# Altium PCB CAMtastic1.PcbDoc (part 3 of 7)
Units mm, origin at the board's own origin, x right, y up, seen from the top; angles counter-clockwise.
Board outline 150.22 x 135.24 mm, 5 copper layers (Top Layer, Layer 1, Mid-Layer 1, Layer 2, Bottom Layer), stack 0.461 mm thick; 0 components, 362 nets, 2885 pads, 0 vias.
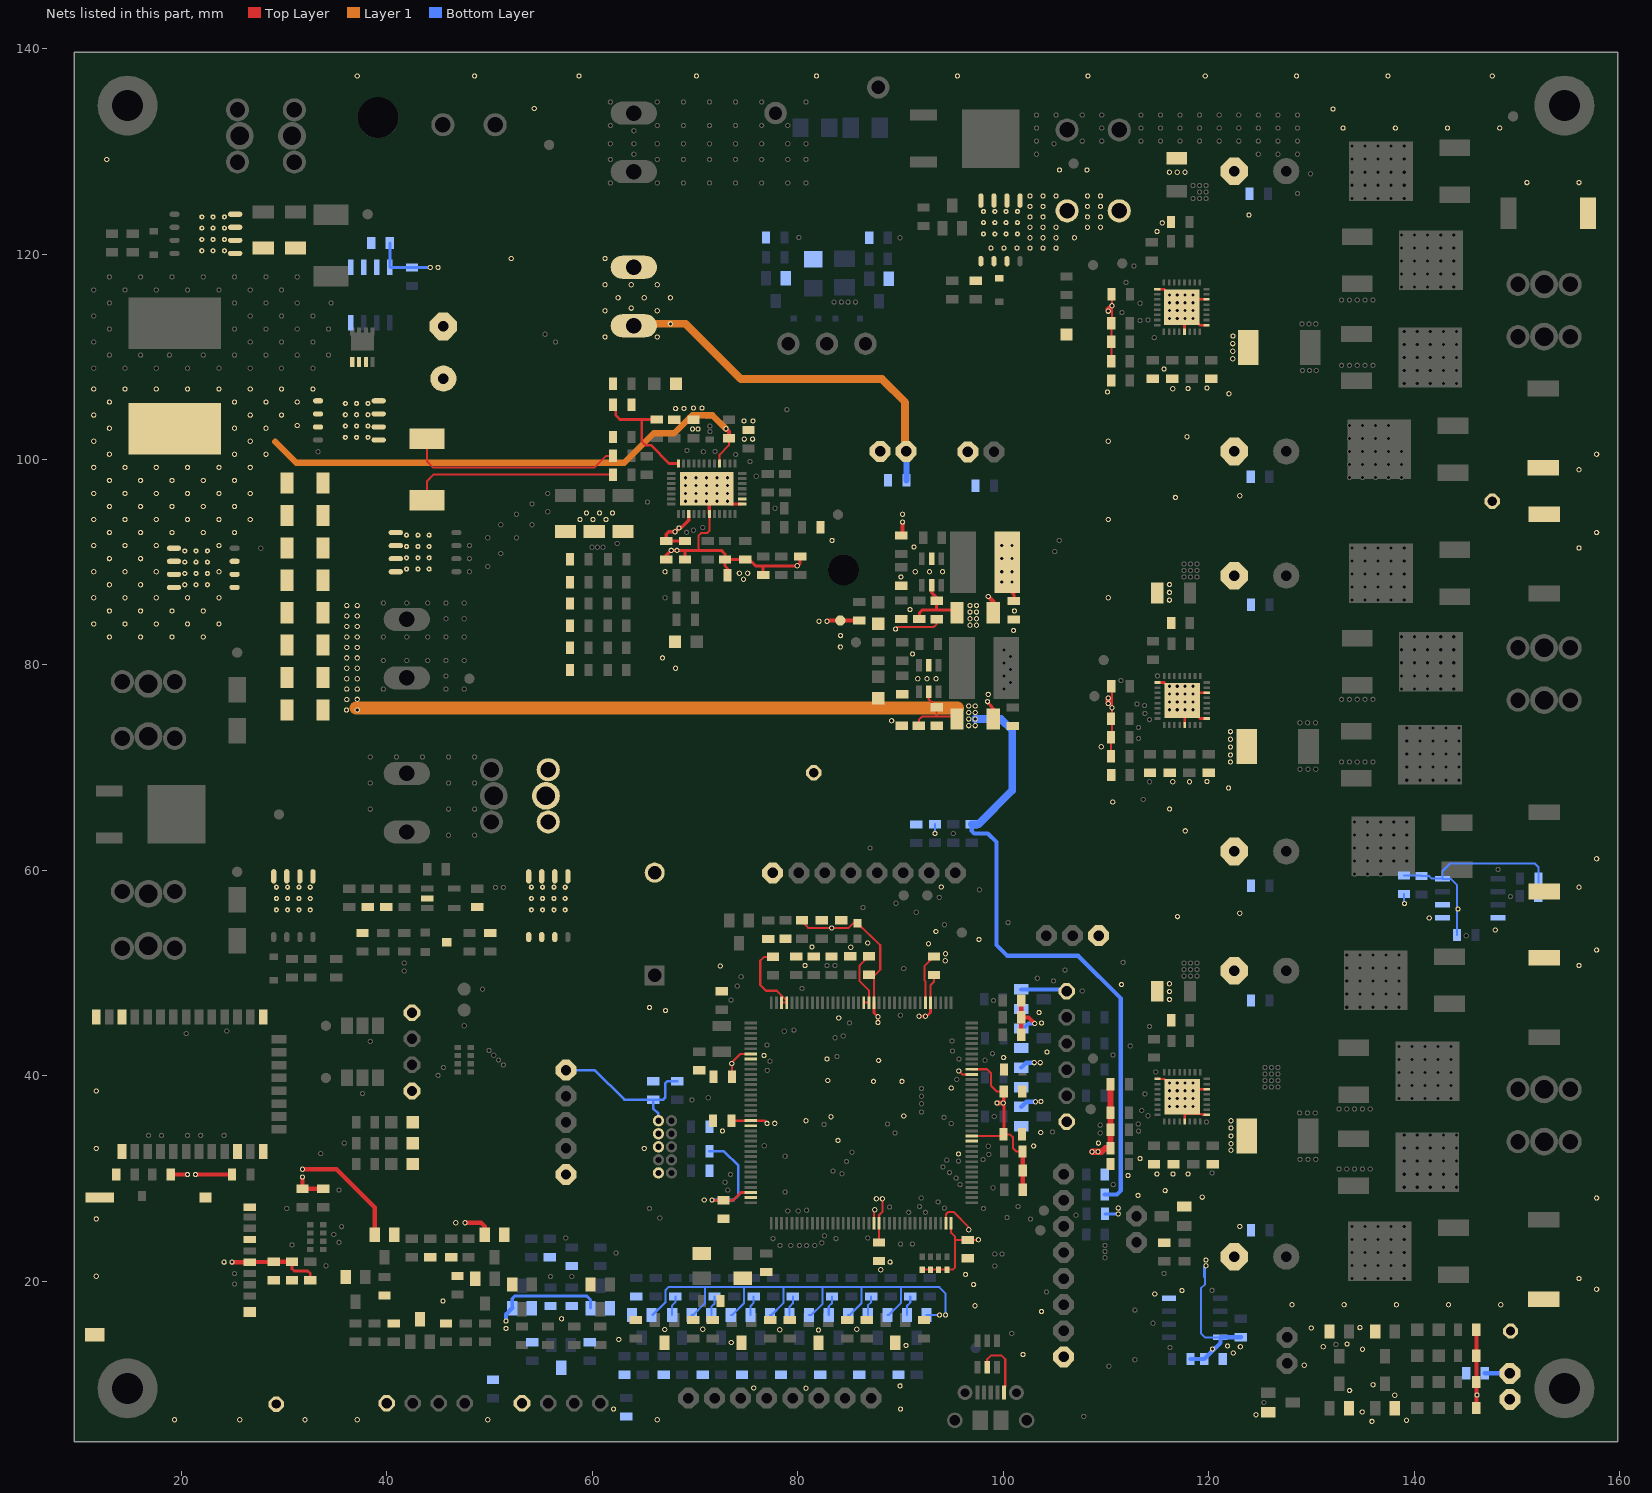
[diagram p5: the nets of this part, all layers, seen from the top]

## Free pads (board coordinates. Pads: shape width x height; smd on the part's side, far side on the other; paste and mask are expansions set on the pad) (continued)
  rect 0.279x1.219 smd paste+0 mask+0.102: 1(77.411,25.654) 1(77.411,47.142) 1(77.911,25.654) 1(77.911,47.142) 1(78.411,25.654) 1(78.411,47.142) 1(78.911,25.654) 1(78.911,47.142) 1(79.411,25.654) 1(79.411,47.142) 1(79.911,25.654) 1(79.911,47.142) 1(80.411,25.654) 1(80.411,47.142) 1(80.911,25.654) 1(80.911,47.142) 1(81.411,25.654) 1(81.411,47.142) 1(81.911,25.654) 1(81.911,47.142) 1(82.411,25.654) 1(82.411,47.142) 1(82.911,25.654) 1(82.911,47.142) 1(83.411,25.654) 1(83.411,47.142) 1(83.911,25.654) 1(83.911,47.142) 1(84.411,25.654) 1(84.411,47.142) 1(84.911,25.654) 1(84.911,47.142) 1(85.411,25.654) 1(85.411,47.142) 1(85.911,25.654) 1(85.911,47.142) 1(86.411,25.654) 1(86.411,47.142) 1(86.911,25.654) 1(86.911,47.142) 1(87.411,25.654) 1(87.411,47.142) 1(87.911,25.654) 1(87.911,47.142) 1(88.411,25.654) 1(88.411,47.142) 1(88.911,25.654) 1(88.911,47.142) 1(89.411,25.654) 1(89.411,47.142) 1(89.911,25.654) 1(89.911,47.142) 1(90.411,25.654) 1(90.411,47.142) 1(90.911,25.654) 1(90.911,47.142) 1(91.411,25.654) 1(91.411,47.142) 1(91.911,25.654) 1(91.911,47.142) 1(92.411,25.654) 1(92.411,47.142) 1(92.911,25.654) 1(92.911,47.142) 1(93.411,25.654) 1(93.411,47.142) 1(93.911,25.654) 1(93.911,47.142) 1(94.411,25.654) 1(94.411,47.142) 1(94.911,25.654) 1(94.911,47.142)
  oct 1.93x1.93 / inner round 1.784 / far side oct 1.93x1.93 hole 1.016 rot 135 mask+0.102: 1(77.545,59.758) 1(88.006,100.804) 1(90.546,100.804) 1(96.549,100.754) 1(99.088,100.754) 1(109.275,53.645)
  round 2.184 hole 1.3 mask+0.102: 1(77.825,133.722) 1(79.075,111.272) 1(82.825,111.272) 1(86.575,111.272) 1(87.825,136.222)
  rect 0.6x0.6 smd far side paste+0 mask+0.102: 1(79.593,113.716) 1(81.992,113.716) 1(83.657,113.716) 1(86.056,113.716)
  rect 1.6x1.8 smd far side paste+0 mask+0.102: 1(80.255,132.296) 1(83.055,132.296)
  rect 1.8x1.6 smd far side paste+0 mask+0.102: 1(81.487,116.685) 1(81.487,119.485)
  round 3 hole 3 mask+0.102: 1(84.435,89.258)
  rect 2x1.6 smd far side paste+0 mask+0.102: 1(84.535,116.761) 1(84.535,119.561)
  rect 1.6x2 smd far side paste+0 mask+0.102: 1(85.157,132.296) 1(87.957,132.296)
  rect 0.8x0.8 smd paste+0 mask+0.102: 1(85.805,53.352) 1(85.805,54.852)
  rect 0.55x1.2 smd paste+0 mask+0.102: 1(91.79,77.389) 1(91.79,79.989) 1(92.069,87.752) 1(92.069,90.352) 1(92.739,77.389) 1(92.739,79.989) 1(93.019,87.752) 1(93.019,90.352) 1(93.689,77.389) 1(93.689,79.989) 1(93.969,87.752) 1(93.969,90.352) 1(97.479,11.628) 1(97.479,14.229) 1(98.429,11.628) 1(98.429,14.229) 1(99.379,11.628) 1(99.379,14.229)
  rect 0.5x0.65 smd paste+0 mask+0.102: 1(92.098,21.143) 1(92.098,22.393) 1(92.898,21.143) 1(92.898,22.393) 1(93.698,21.143) 1(93.698,22.393) 1(94.498,21.143) 1(94.498,22.393)
  round 1.508 hole 1 mask+0.102: 1(95.27,6.469) 1(102.27,6.469)
  rect 2.5x6 smd paste+0 mask+0.102: 1(95.974,79.705) 1(96.075,89.992) 1(100.274,79.705) 1(100.375,89.992)
  round 1.45 hole 0.85 mask+0.102: 1(96.27,9.169) 1(101.27,9.169)
  rect 0.4x1.35 smd paste+0 mask+0.102: 1(97.47,9.169) 1(98.12,9.169) 1(98.77,9.169) 1(99.42,9.169) 1(100.07,9.169)
  rect 1.5x1.9 smd paste+0 mask+0.102: 1(97.77,6.469) 1(99.77,6.469)
  rect 1.4x1 smd far side paste+0 mask+0.102: 1(101.749,35.093) 1(101.749,36.993) 1(101.749,38.903) 1(101.749,40.803) 1(101.749,42.713) 1(101.749,44.613) 1(101.749,46.523) 1(101.749,48.423) 1(103.949,36.043) 1(103.949,39.853) 1(103.949,43.663) 1(103.949,47.473)
  rect 1.2x2 smd paste+0 mask+0.102: 1(114.967,48.24) 1(114.967,87.007) 1(118.167,48.24) 1(118.167,87.007)
  rect 0.6x0.25 smd paste+0 mask+0.102: 1(114.98,113.083) 1(114.98,113.583) 1(114.98,114.083) 1(114.98,114.583) 1(114.98,115.083) 1(114.98,115.583) 1(114.98,116.083) 1(114.98,116.583) 1(115.005,36.203) 1(115.005,36.703) 1(115.005,37.203) 1(115.005,37.703) 1(115.005,38.203) 1(115.005,38.703) 1(115.005,39.203) 1(115.005,39.703) 1(115.005,74.792) 1(115.005,75.292) 1(115.005,75.792) 1(115.005,76.292) 1(115.005,76.792) 1(115.005,77.292) 1(115.005,77.792) 1(115.005,78.292) 1(119.78,113.083) 1(119.78,113.583) 1(119.78,114.083) 1(119.78,114.583) 1(119.78,115.083) 1(119.78,115.583) 1(119.78,116.083) 1(119.78,116.583) 1(119.805,36.203) 1(119.805,36.703) 1(119.805,37.203) 1(119.805,37.703) 1(119.805,38.203) 1(119.805,38.703) 1(119.805,39.203) 1(119.805,39.703) 1(119.805,74.792) 1(119.805,75.292) 1(119.805,75.792) 1(119.805,76.292) 1(119.805,76.792) 1(119.805,77.292) 1(119.805,77.792) 1(119.805,78.292)
  rect 1.4x1 smd paste+0 mask+0.102: 1(115.414,26.34) 1(117.614,25.39) 1(117.614,27.29) 1(125.781,7.254) 1(125.781,9.154) 1(128.181,8.204)
  rect 0.25x0.6 smd paste+0 mask+0.102: 1(115.63,112.433) 1(115.63,117.233) 1(115.655,35.553) 1(115.655,40.353) 1(115.655,74.142) 1(115.655,78.942) 1(116.13,112.433) 1(116.13,117.233) 1(116.155,35.553) 1(116.155,40.353) 1(116.155,74.142) 1(116.155,78.942) 1(116.63,112.433) 1(116.63,117.233) 1(116.655,35.553) 1(116.655,40.353) 1(116.655,74.142) 1(116.655,78.942) 1(117.13,112.433) 1(117.13,117.233) 1(117.155,35.553) 1(117.155,40.353) 1(117.155,74.142) 1(117.155,78.942) 1(117.63,112.433) 1(117.63,117.233) 1(117.655,35.553) 1(117.655,40.353) 1(117.655,74.142) 1(117.655,78.942) 1(118.13,112.433) 1(118.13,117.233) 1(118.155,35.553) 1(118.155,40.353) 1(118.155,74.142) 1(118.155,78.942) 1(118.63,112.433) 1(118.63,117.233) 1(118.655,35.553) 1(118.655,40.353) 1(118.655,74.142) 1(118.655,78.942) 1(119.13,112.433) 1(119.13,117.233) 1(119.155,35.553) 1(119.155,40.353) 1(119.155,74.142) 1(119.155,78.942)
  rect 1.4x0.52 smd far side paste+0 mask+0.102: 1(116.124,14.554) 1(116.124,15.824) 1(116.124,17.094) 1(116.124,18.364) 1(121.125,14.554) 1(121.125,15.824) 1(121.125,17.094) 1(121.125,18.364)
  rect 2x1.2 smd paste+0 mask+0.102: 1(116.872,126.111) 1(116.872,129.311)
  rect 3.45x3.45 smd paste+0 mask+0.102: 1(117.38,114.833) 1(117.405,37.953) 1(117.405,76.542)
  oct 2.54x2.54 / inner round 2.347 / far side oct 2.54x2.54 hole 1.016 rot 45 mask+0.102: 1(122.46,22.403) 1(122.46,50.241) 1(122.46,61.849) 1(122.46,88.697) 1(122.46,100.787) 1(122.46,128.067)
  rect 2x3.4 smd paste+0 mask+0.102: 1(123.676,34.169) 1(123.702,72.072) 1(123.854,110.896) 1(129.676,34.169) 1(129.702,72.072) 1(129.854,110.896)
  rect 3x1.6 smd paste+0 mask+0.102: 1(134.093,29.318) 1(134.093,33.888) 1(134.114,38.183) 1(134.114,42.753) 1(134.347,68.974) 1(134.347,73.544) 1(134.373,107.646) 1(134.373,112.216) 1(134.444,78.017) 1(134.444,82.587) 1(134.444,117.12) 1(134.444,121.69) 1(143.435,47.036) 1(143.435,51.606) 1(143.771,98.705) 1(143.771,103.275) 1(143.821,20.646) 1(143.821,25.216) 1(143.943,86.628) 1(143.943,91.198) 1(143.943,125.782) 1(143.943,130.352) 1(144.152,60.06) 1(144.152,64.63)
  rect 6.2x5.8 smd paste+0 mask+0.102: 1(136.255,49.321) 1(136.591,100.99) 1(136.641,22.931) 1(136.763,88.913) 1(136.763,128.067) 1(136.972,62.345) 1(141.273,31.603) 1(141.294,40.468) 1(141.527,71.259) 1(141.624,80.302) 1(141.624,119.405)
  rect 6.2x5.8 / inner round 0.508 / far side round 0.508 hole 0.305 mask+0.102: 1(141.553,109.931)
  round 0.508 smd paste-0.254 mask+0.61: 1(141.558,109.931)
  rect 1.5x0.55 smd far side paste+0 mask+0.102: 1(142.747,55.397) 1(142.747,56.667) 1(142.747,57.937) 1(142.747,59.207) 1(148.147,55.397) 1(148.147,56.667) 1(148.147,57.937) 1(148.147,59.207)
  rect 1.52x3.07 smd paste+0 mask+0.102: 1(149.176,123.977) 1(156.907,123.977)
  rect 3.07x1.52 smd paste+0 mask+0.102: 1(152.559,99.183) 1(152.559,106.913) 1(152.584,18.264) 1(152.584,25.994) 1(152.635,43.765) 1(152.635,51.496) 1(152.635,86.952) 1(152.635,94.682) 1(152.661,57.945) 1(152.661,65.676)

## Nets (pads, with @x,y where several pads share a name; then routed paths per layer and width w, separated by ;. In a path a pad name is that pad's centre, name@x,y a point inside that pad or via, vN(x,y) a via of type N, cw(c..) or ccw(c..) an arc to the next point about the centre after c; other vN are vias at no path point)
$Net0: pad.1@11.542,14.818 pad.1@11.692,45.738 pad.1@11.705,20.498 pad.1@11.705,26.086 pad.1@11.705,32.944 pad.1@11.705,38.532 pad.1@12.042,28.168 pad.1@12.721,129.21 pad.1@13.637,30.404 pad.1@14.206,32.631 pad.1@14.206,45.738 pad.1@19.325,6.528 pad.1@21.973,120.321 pad.1@21.973,121.421 pad.1@21.973,122.521 pad.1@21.973,123.621 pad.1@22.342,28.168 pad.1@23.073,120.321 pad.1@23.073,121.421 pad.1@23.073,122.521 pad.1@23.073,123.621 pad.1@24.173,120.321 pad.1@24.173,121.421 pad.1@24.173,122.521 pad.1@24.173,123.621 pad.1@25.167,87.554 pad.1@25.167,88.824 pad.1@25.167,90.094 pad.1@25.222,120.066 pad.1@25.222,121.336 pad.1@25.222,122.606 pad.1@25.222,123.876 pad.1@25.454,32.631 pad.1@25.675,6.528 pad.1@26.642,17.018 pad.1@26.642,24.068 pad.1@26.642,27.218 pad.1@27.953,32.631 pad.1@27.953,45.738 pad.1@27.961,120.597 pad.1@28.977,20.106 pad.1@28.977,59.418 pad.1@29.231,8.052 pad.1@29.232,56.168 pad.1@29.232,57.268 pad.1@29.232,58.368 pad.1@30.27,75.616 pad.1@30.27,78.773 pad.1@30.27,81.929 pad.1@30.27,85.086 pad.1@30.27,88.243 pad.1@30.27,91.4 pad.1@30.27,94.557 pad.1@30.27,97.714 pad.1@30.247,59.418 pad.1@30.332,56.168 pad.1@30.332,57.268 pad.1@30.332,58.368 pad.1@30.755,20.106 pad.1@31.101,120.597 pad.1@31.431,56.168 pad.1@31.431,57.268 pad.1@31.431,58.368 pad.1@31.517,59.418 pad.1@32.025,6.528 pad.1@32.532,56.168 pad.1@32.532,57.268 pad.1@32.532,58.368 pad.1@32.787,59.418 pad.1@35.986,20.428 pad.1@36.47,113.302 pad.1@36.47,118.702 pad.1@37.74,118.702 pad.1@37.105,6.528 pad.1@37.105,137.338 pad.1@37.613,53.91 pad.1@38.48,121.082 pad.1@38.128,56.428 pad.1@39.01,118.702 pad.1@39.755,18.633 pad.1@39.915,56.428 pad.1@39.958,8.136 pad.1@40.669,15.911 pad.1@40.705,24.544 pad.1@42.439,38.532 pad.1@42.507,31.42 pad.1@42.507,33.452 pad.1@42.507,35.484 pad.1@43.209,16.315 pad.1@43.927,57.278 pad.1@44.2,22.341 pad.1@45.445,18.085 pad.1@45.487,112.954 pad.1@45.749,15.911 pad.1@45.825,53.01 pad.1@46.257,22.341 pad.1@46.867,20.534 pad.1@48.535,137.338 pad.1@48.584,20.25 pad.1@48.789,56.428 pad.1@49.805,6.528 pad.1@50.059,53.91 pad.1@50.321,10.425 pad.1@51.424,24.544 pad.1@52.091,119.558 pad.1@52.191,19.691 pad.1@53.141,8.136 pad.1@53.795,53.518 pad.1@54.091,17.391 pad.1@54.157,14.083 pad.1@54.335,134.163 pad.1@55.065,53.518 pad.1@55.859,22.341 pad.1@55.909,17.591 pad.1@56.335,53.518 pad.1@56.951,11.6 pad.1@57.002,16.358 pad.1@57.81,79.509 pad.1@57.81,81.668 pad.1@57.81,83.827 pad.1@57.81,85.986 pad.1@57.81,88.044 pad.1@57.81,90.304 pad.1@57.383,92.987 pad.1@57.425,30.404 pad.1@57.992,17.591 pad.1@57.992,21.503 pad.1@58.78,94.158 pad.1@58.695,137.338 pad.1@59.415,94.793 pad.1@59.745,14.083 pad.1@59.811,19.691 pad.1@60.05,94.158 pad.1@60.177,92.987 pad.1@60.685,94.793 pad.1@61.32,94.158 pad.1@61.711,17.391 pad.1@61.955,94.793 pad.1@62.056,7.569 pad.1@62.564,14.351 pad.1@62.971,92.987 pad.1@63.123,10.911 pad.1@63.301,6.847 pad.1@63.797,105.334 pad.1@63.841,16.729 pad.1@64.215,16.242 pad.1@64.266,18.531 pad.1@65.045,32.944 pad.1@65.553,46.66 pad.1@65.917,39.483 pad.1@66.061,59.788 pad.1@66.315,6.528 pad.1@66.425,30.556 pad.1@66.425,33.096 pad.1@66.425,34.366 pad.1@66.823,80.696 pad.1@66.933,10.911 pad.1@67.009,14.038 pad.1@67.19,90.261 pad.1@67.035,15.316 pad.1@67.67,91.161 pad.1@67.077,89.078 pad.1@67.111,46.355 pad.1@67.761,16.721 pad.1@67.977,103.872 pad.1@68.042,82.263 pad.1@68.076,18.531 pad.1@68.093,79.68 pad.1@68.101,104.953 pad.1@68.127,107.366 pad.1@68.228,91.161 pad.1@68.914,104.978 pad.1@69.006,90.273 pad.1@69.067,95.936 pad.1@69.067,96.698 pad.1@69.067,97.46 pad.1@69.067,98.222 pad.1@69.752,102.972 pad.1@69.803,16.242 pad.1@69.829,105.004 pad.1@69.831,103.872 pad.1@70.083,95.936 pad.1@70.083,96.698 pad.1@70.083,97.46 pad.1@70.083,98.222 pad.1@70.125,137.338 pad.1@70.286,102.972 pad.1@70.413,40.553 pad.1@70.648,22.714 pad.1@70.667,105.004 pad.1@70.743,10.911 pad.1@70.743,15.342 pad.1@71.099,95.936 pad.1@71.099,96.698 pad.1@71.099,97.46 pad.1@71.099,98.222 pad.1@71.127,97.155 pad.1@71.377,94.703 pad.1@71.389,30.759 pad.1@71.389,35.052 pad.1@71.571,16.721 pad.1@71.708,16.242 pad.1@71.748,35.636 pad.1@71.774,39.929 pad.1@71.886,18.531 pad.1@72.75,26.1 pad.1@72.115,95.936 pad.1@72.115,96.698 pad.1@72.115,97.46 pad.1@72.115,98.222 pad.1@72.445,50.698 pad.1@72.456,18.085 pad.1@72.597,48.246 pad.1@72.648,34.646 pad.1@72.905,90.261 pad.1@73.131,95.936 pad.1@73.131,96.698 pad.1@73.131,97.46 pad.1@73.131,98.222 pad.1@73.144,88.748 pad.1@73.512,14.046 pad.1@74.299,88.925 pad.1@74.502,14.038 pad.1@74.553,10.911 pad.1@74.579,95.655 pad.1@74.579,96.155 pad.1@74.648,20.314 pad.1@74.705,88.341 pad.1@74.756,103.759 pad.1@74.782,101.981 pad.1@74.861,90.261 pad.1@75.62,103.759 pad.1@75.112,88.925 pad.1@75.191,102.881 pad.1@75.381,16.721 pad.1@75.417,28.148 pad.1@75.417,35.148 pad.1@75.417,41.648 pad.1@75.594,101.981 pad.1@75.696,9.627 pad.1@75.696,18.531 pad.1@76.613,88.762 pad.1@76.712,41.986 pad.1@76.905,121.61 pad.1@76.915,20.919 pad.1@77.118,53.329 pad.1@77.296,16.242 pad.1@77.545,59.758 pad.1@77.576,51.598 pad.1@78.236,15.291 pad.1@78.363,10.911 pad.1@78.411,47.142 pad.1@78.795,53.354 pad.1@78.805,117.63 pad.1@78.911,47.142 pad.1@79.191,16.721 pad.1@79.201,16.242 pad.1@79.506,18.531 pad.1@79.836,51.624 pad.1@79.938,89.662 pad.1@80.7,50.749 pad.1@80.217,90.559 pad.1@80.776,9.601 pad.1@80.776,35.636 pad.1@81.36,52.553 pad.1@81.487,119.485 pad.1@81.538,51.624 pad.1@81.555,69.52 pad.1@81.809,137.338 pad.1@81.995,14.038 pad.1@81.995,15.265 pad.1@82.2,93.396 pad.1@82.91,39.548 pad.1@82.173,10.911 pad.1@82.325,55.154 pad.1@82.833,41.656 pad.1@83.001,16.721 pad.1@83.214,36.017 pad.1@83.265,51.624 pad.1@83.316,18.531 pad.1@83.333,92.126 pad.1@83.905,33.727 pad.1@83.976,45.644 pad.1@84.23,55.154 pad.1@84.129,81.763 pad.1@84.154,82.855 pad.1@84.789,16.242 pad.1@85.094,51.649 pad.1@85.145,52.527 pad.1@85.729,15.342 pad.1@85.983,10.911 pad.1@86.411,47.142 pad.1@86.694,16.242 pad.1@86.796,52.934 pad.1@86.811,16.721 pad.1@86.911,47.142 pad.1@86.923,51.649 pad.1@86.955,121.59 pad.1@87.126,18.531 pad.1@87.355,39.472 pad.1@87.411,25.654 pad.1@87.482,26.975 pad.1@87.837,76.75 pad.1@87.837,84.015 pad.1@87.863,41.504 pad.1@87.888,21.985 pad.1@88.006,100.804 pad.1@88.066,21.133 pad.1@88.98,21.869 pad.1@88.783,97.968 pad.1@88.855,117.61 pad.1@89.128,74.574 pad.1@89.488,14.038 pad.1@89.514,83.49 pad.1@89.793,10.911 pad.1@89.945,9.83 pad.1@89.996,7.569 pad.1@90.022,88.57 pad.1@90.53,13.767 pad.1@90.072,84.469 pad.1@90.072,87.721 pad.1@90.123,39.472 pad.1@90.123,74.081 pad.1@90.149,77.154 pad.1@90.301,36.093 pad.1@90.621,16.721 pad.1@90.911,85.395 pad.1@90.936,18.531 pad.1@91.52,64.476 pad.1@91.165,81.077 pad.1@91.292,91.491 pad.1@91.419,89.078 pad.1@91.673,78.664 pad.1@92.282,16.242 pad.1@92.411,47.142 pad.1@92.562,78.664 pad.1@92.714,52.857 pad.1@92.739,79.989 pad.1@92.816,89.078 pad.1@93.019,90.352 pad.1@93.247,51.624 pad.1@93.425,54.051 pad.1@93.451,78.664 pad.1@93.501,74.081 pad.1@93.501,84.444 pad.1@93.959,58.395 pad.1@94.34,51.206 pad.1@94.086,89.078 pad.1@94.365,51.892 pad.1@94.411,25.654 pad.1@94.924,38.811 pad.1@95.66,40.488 pad.1@95.525,137.338 pad.1@95.635,32.41 pad.1@96.321,20.676 pad.1@96.524,22.239 pad.1@96.549,100.754 pad.1@96.626,25.019 pad.1@96.905,33.648 pad.1@96.905,40.148 pad.1@97.108,19.685 pad.1@97.235,17.628 pad.1@97.289,97.46 pad.1@97.303,117.41 pad.1@97.616,53.289 pad.1@97.811,119.304 pad.1@98.429,11.628 pad.1@98.454,76.429 pad.1@98.531,77.14 pad.1@98.531,86.665 pad.1@99.016,74.727 pad.1@99.016,85.09 pad.1@99.081,119.304 pad.1@99.589,117.66 pad.1@100.07,9.169 pad.1@100.029,41.783 pad.1@100.069,40.615 pad.1@100.351,119.304 pad.1@100.918,74.055 pad.1@100.994,83.363 pad.1@101.02,84.419 pad.1@101.071,85.268 pad.1@101.749,35.093 pad.1@101.749,38.903 pad.1@101.749,42.713 pad.1@101.749,46.523 pad.1@101.818,34.315 pad.1@101.844,38.481 pad.1@101.909,12.878 pad.1@102.95,33.172 pad.1@103.484,46.177 pad.1@103.636,34.493 pad.1@103.712,17.069 pad.1@104.246,42.316 pad.1@105.465,128.194 pad.1@105.871,12.649 pad.1@106.151,35.535 pad.1@106.151,112.171 pad.1@108.132,128.194 pad.1@108.225,137.338 pad.1@109.249,33.452 pad.1@109.275,53.645 pad.1@109.529,72.034 pad.1@109.873,30.404 pad.1@110.43,31.42 pad.1@110.138,106.578 pad.1@110.215,86.538 pad.1@110.215,94.158 pad.1@110.215,101.778 pad.1@110.506,69.291 pad.1@110.511,107.696 pad.1@110.646,66.65 pad.1@111.485,48.895 pad.1@112.145,30.302 pad.1@113.11,28.372 pad.1@113.313,31.953 pad.1@114.66,31.409 pad.1@114.98,116.583 pad.1@114.279,69.509 pad.1@114.533,107.863 pad.1@114.736,18.771 pad.1@114.939,30.455 pad.1@114.964,122.199 pad.1@114.967,48.24 pad.1@114.967,87.007 pad.1@115.005,39.703 pad.1@115.005,78.292 pad.1@115.65,23.76 pad.1@115.65,108.814 pad.1@115.472,123.038 pad.1@115.752,28.829 pad.1@116.92,37.033 pad.1@116.92,37.795 pad.1@116.92,38.557 pad.1@116.92,39.319 pad.1@116.92,75.641 pad.1@116.92,76.403 pad.1@116.92,77.165 pad.1@116.92,77.927 pad.1@116.92,113.741 pad.1@116.92,114.503 pad.1@116.92,115.265 pad.1@116.92,116.027 pad.1@116.92,127.965 pad.1@116.124,18.364 pad.1@116.158,37.033 pad.1@116.158,37.795 pad.1@116.158,38.557 pad.1@116.158,39.319 pad.1@116.158,47.447 pad.1@116.158,48.209 pad.1@116.158,48.971 pad.1@116.158,75.641 pad.1@116.158,76.403 pad.1@116.158,77.165 pad.1@116.158,77.927 pad.1@116.158,86.309 pad.1@116.158,87.071 pad.1@116.158,87.833 pad.1@116.158,113.741 pad.1@116.158,114.503 pad.1@116.158,115.265 pad.1@116.158,116.027 pad.1@116.158,127.965 pad.1@116.184,65.989 pad.1@116.184,69.509 pad.1@116.328,123.114 pad.1@116.353,45.421 pad.1@116.353,84.086 pad.1@116.438,107.863 pad.1@116.488,68.631 pad.1@116.488,106.883 pad.1@116.514,30.455 pad.1@116.565,31.409 pad.1@116.742,96.317 pad.1@116.872,129.311 pad.1@116.946,55.499 pad.1@117.38,114.833 pad.1@117.63,112.433 pad.1@117.377,19.101 pad.1@117.405,37.953 pad.1@117.405,76.542 pad.1@117.614,27.29 pad.1@117.655,35.553 pad.1@117.655,74.142 pad.1@117.682,37.033 pad.1@117.682,37.795 pad.1@117.682,38.557 pad.1@117.682,39.319 pad.1@117.682,75.641 pad.1@117.682,76.403 pad.1@117.682,77.165 pad.1@117.682,77.927 pad.1@117.682,113.741 pad.1@117.682,114.503 pad.1@117.682,115.265 pad.1@117.682,116.027 pad.1@117.682,127.965 pad.1@117.708,63.856 pad.1@117.885,102.21 pad.1@117.987,30.455 pad.1@117.987,106.909 pad.1@118.114,68.631 pad.1@118.444,37.033 pad.1@118.444,37.795 pad.1@118.444,38.557 pad.1@118.444,39.319 pad.1@118.444,75.641 pad.1@118.444,76.403 pad.1@118.444,77.165 pad.1@118.444,77.927 pad.1@118.444,113.741 pad.1@118.444,114.503 pad.1@118.444,115.265 pad.1@118.444,116.027 pad.1@119.78,113.083 pad.1@119.78,115.583 pad.1@119.359,28.194 pad.1@119.655,137.338 pad.1@119.805,36.203 pad.1@119.805,38.703 pad.1@119.805,74.792 pad.1@119.805,77.292 pad.1@119.816,68.656 pad.1@119.816,106.959 pad.1@119.994,69.509 pad.1@120.248,107.863 pad.1@120.375,31.409 pad.1@121.353,12.446 pad.1@121.822,13.716 pad.1@121.924,68.021 pad.1@121.949,106.401 pad.1@122.46,22.403 pad.1@122.46,50.241 pad.1@122.46,61.849 pad.1@122.46,88.697 pad.1@122.46,100.787 pad.1@122.46,128.067 pad.1@122.102,70.561 pad.1@122.102,71.247 pad.1@122.102,72.009 pad.1@122.102,72.771 pad.1@122.102,73.508 pad.1@122.153,32.766 pad.1@122.153,33.401 pad.1@122.153,34.163 pad.1@122.153,34.925 pad.1@122.153,35.636 pad.1@122.328,109.804 pad.1@122.328,110.541 pad.1@122.328,111.277 pad.1@122.353,112.014 pad.1@122.381,13.03 pad.1@123.016,25.349 pad.1@123.016,55.829 pad.1@123.016,96.469 pad.1@123.067,13.64 pad.1@123.676,34.169 pad.1@123.702,72.072 pad.1@123.854,110.896 pad.1@123.905,123.8 pad.1@123.971,125.882 pad.1@124.072,98.323 pad.1@124.098,24.968 pad.1@124.098,47.346 pad.1@124.098,58.496 pad.1@124.098,85.877 pad.1@124.591,7.01 pad.1@125.781,7.254 pad.1@128.096,17.729 pad.1@128.545,137.338 pad.1@129.29,11.836 pad.1@129.976,15.469 pad.1@131.144,13.64 pad.1@131.746,15.119 pad.1@132.084,134.112 pad.1@133.71,9.373 pad.1@133.075,132.258 pad.1@133.176,17.729 pad.1@133.456,13.894 pad.1@133.646,7.639 pad.1@134.7,15.494 pad.1@134.929,7.29 pad.1@134.954,13.386 pad.1@135.869,6.375 pad.1@135.996,9.931 pad.1@136.191,15.119 pad.1@137.435,137.338 pad.1@138.091,7.639 pad.1@138.104,8.915 pad.1@138.155,132.258 pad.1@138.256,17.729 pad.1@138.995,57.698 pad.1@139.046,56.769 pad.1@139.247,6.477 pad.1@141.459,55.372 pad.1@142.747,55.397 pad.1@142.747,56.667 pad.1@143.235,132.258 pad.1@143.336,17.729 pad.1@145.053,11.049 pad.1@147.595,95.936 pad.1@147.595,137.338 pad.1@147.885,54.204 pad.1@148.147,55.397 pad.1@148.315,132.258 pad.1@148.416,17.729 pad.1@149.305,8.509 pad.1@149.373,15.164 pad.1@150.956,126.949 pad.1@152.559,99.183 pad.1@152.584,18.264 pad.1@152.635,51.496 pad.1@152.635,94.682 pad.1@152.661,57.945 pad.1@156.036,20.269 pad.1@156.036,50.749 pad.1@156.036,58.369 pad.1@156.036,91.389 pad.1@156.036,99.009 pad.1@156.036,126.949 pad.1@156.907,123.977 pad.1@157.755,19.228 pad.1@157.755,28.118 pad.1@157.755,52.248 pad.1@157.755,61.138 pad.1@157.755,92.888 pad.1@157.755,100.508 | length 118.5
  Top Layer w0.203: 70.311,91.161 70.311,92.583 70.565,92.837 71.149,92.837 71.377,93.064 pad.1@71.377,94.703 ; pad.1@77.576,51.598 77.565,51.587 76.712,51.587 76.331,51.206 76.331,48.844 76.89,48.285 77.957,48.285 78.922,47.32 78.922,47.168 78.911,47.157 pad.1@78.911,47.142 pad.1@78.411,47.142 ; pad.1@86.411,47.142 pad.1@86.911,47.142 86.911,48.323 86.008,49.225 86.008,50.724 86.034,50.749 86.034,50.76 pad.1@86.923,51.649 ; pad.1@87.411,25.654 87.411,26.904 pad.1@87.482,26.975 ; pad.1@89.514,83.49 89.717,83.693 93.222,83.693 93.501,83.972 pad.1@93.501,84.444 ; pad.1@92.411,47.142 92.411,47.141 92.435,47.117 92.435,49.174 92.333,49.276 92.333,50.709 pad.1@93.247,51.624 pad.1@92.892,51.511 ; pad.1@94.416,25.756 94.416,25.654 pad.1@94.411,25.654 94.416,25.659 94.416,26.518 94.644,26.746 95.152,26.746 96.626,25.273 pad.1@96.626,25.019 ; pad.1@95.66,40.488 96,40.148 pad.1@96.905,40.148 ; pad.1@98.429,11.628 98.429,12.421 98.81,12.802 99.801,12.802 100.182,12.421 100.182,9.703 100.08,9.601 100.08,8.748 pad.1@100.07,9.169 pad.1@100.055,8.839 ; pad.1@114.837,116.586 pad.1@114.98,116.583 ; pad.1@115.005,39.703 115.015,39.7 115.65,39.7 117.301,38.049 pad.1@117.405,37.953 ; pad.1@116.793,38.684 pad.1@117.405,37.953 ; pad.1@117.655,35.553 117.657,35.636 pad.1@117.657,36.271 ; pad.1@119.714,38.71 pad.1@119.805,38.703 ; pad.1@119.805,36.203 119.663,36.22 119.409,36.22 119.333,36.271 pad.1@117.657,36.271 ; pad.1@117.405,37.953 pad.1@117.657,36.271 ; pad.1@117.405,37.953 117.428,37.922 117.682,37.668 pad.1@117.657,36.271
  Top Layer w0.254: pad.1@114.98,116.583 115.63,116.583 pad.1@117.38,114.833 ; pad.1@115.005,78.292 115.655,78.292 pad.1@117.405,76.542 119.155,74.792 pad.1@119.805,74.792 ; pad.1@116.793,38.684 pad.1@119.714,38.71 ; pad.1@117.63,112.433 117.63,114.583 pad.1@117.38,114.833 ; pad.1@117.655,74.142 pad.1@117.655,76.292 ; pad.1@118.155,77.292 pad.1@119.805,77.292 ; pad.1@119.78,113.083 119.13,113.083 pad.1@117.38,114.833 ; pad.1@119.78,115.583 118.13,115.583 pad.1@117.38,114.833
  Top Layer w0.305: pad.1@67.19,90.261 67.19,90.681 pad.1@67.67,91.161 69.168,91.161 ; pad.1@69.006,90.273 69.006,91.145 69.168,91.161 ; pad.1@71.099,95.936 71.377,95.658 pad.1@71.377,94.703 ; pad.1@73.131,95.936 73.412,95.655 pad.1@74.579,95.655 ; pad.1@73.144,88.748 73.144,89.394 72.902,89.637 72.902,90.258 pad.1@72.905,90.261 ; pad.1@76.613,88.762 76.613,89.589 76.661,89.637 ; pad.1@80.217,90.559 80.217,89.916 79.938,89.637 76.661,89.637 ; pad.1@98.454,76.429 99.016,75.766 pad.1@99.016,74.727 ; pad.1@117.655,76.292 pad.1@117.405,76.542 pad.1@118.155,77.292 ; 69.168,91.161 70.311,91.161 72.546,91.161 72.902,90.805 72.902,90.263 pad.1@72.905,90.261 ; pad.1@72.905,90.261 pad.1@74.861,90.261 75.275,90.261 75.899,89.637 76.661,89.637
  Top Layer w0.406: pad.1@98.531,86.665 99.016,86.18 pad.1@99.016,85.09
  Bottom Layer w0.203: pad.1@67.761,16.721 67.761,17.668 68.076,17.983 pad.1@68.076,18.531 ; pad.1@71.571,16.721 71.571,17.516 71.886,17.831 pad.1@71.886,18.531 ; pad.1@75.381,16.721 75.381,17.592 75.696,17.907 pad.1@75.696,18.531 ; pad.1@79.191,16.721 79.191,17.541 79.506,17.856 pad.1@79.506,18.531 ; pad.1@83.001,16.721 83.001,17.567 83.316,17.882 pad.1@83.316,18.531 ; pad.1@86.811,16.721 86.811,17.668 87.126,17.983 pad.1@87.126,18.531 ; pad.1@90.621,16.721 90.621,17.617 90.936,17.932 pad.1@90.936,18.531 ; pad.1@138.995,57.698 138.995,56.82 pad.1@139.046,56.769
$Net1: pad.1@53.795,59.418 pad.1@54.05,56.168 pad.1@54.05,57.268 pad.1@54.05,58.368 pad.1@55.7,64.718 pad.1@55.7,69.798 pad.1@55.065,59.418 pad.1@55.149,56.168 pad.1@55.149,57.268 pad.1@55.149,58.368 pad.1@55.475,67.258 pad.1@56.25,56.168 pad.1@56.25,57.268 pad.1@56.25,58.368 pad.1@56.335,59.418 pad.1@57.35,56.168 pad.1@57.35,57.268 pad.1@57.35,58.368 pad.1@57.605,59.418
$Net2: pad.1@40.857,89.078 pad.1@40.857,90.348 pad.1@40.857,91.618 pad.1@40.857,92.888 pad.1@41.907,89.333 pad.1@41.907,90.433 pad.1@41.907,91.533 pad.1@41.907,92.633 pad.1@43.007,89.333 pad.1@43.007,90.433 pad.1@43.007,91.533 pad.1@43.007,92.633 pad.1@43.906,96.032 pad.1@44.107,89.333 pad.1@44.107,90.433 pad.1@44.107,91.533 pad.1@44.107,92.633 pad.1@61.997,98.527 | length 20.2
  Top Layer w0.203: pad.1@43.906,96.032 43.906,97.911 44.521,98.527 pad.1@61.997,98.527
$Net3: pad.1@33.779,75.616 pad.1@33.779,78.773 pad.1@33.779,81.929 pad.1@33.779,85.086 pad.1@33.779,88.243 pad.1@33.779,91.4 pad.1@33.779,94.557 pad.1@33.779,97.714 pad.1@35.943,102.16 pad.1@35.943,103.26 pad.1@35.943,104.36 pad.1@35.943,105.46 pad.1@36.063,75.616 pad.1@36.089,76.632 pad.1@36.089,77.648 pad.1@36.089,78.664 pad.1@36.089,79.68 pad.1@36.089,80.696 pad.1@36.089,81.712 pad.1@36.089,82.728 pad.1@36.089,83.744 pad.1@36.089,84.76 pad.1@36.089,85.776 pad.1@36.622,109.487 pad.1@37.043,102.16 pad.1@37.043,103.26 pad.1@37.043,104.36 pad.1@37.043,105.46 pad.1@37.105,75.616 pad.1@37.105,76.657 pad.1@37.105,77.648 pad.1@37.105,78.664 pad.1@37.105,79.68 pad.1@37.105,80.696 pad.1@37.105,81.712 pad.1@37.105,82.728 pad.1@37.105,83.744 pad.1@37.105,84.76 pad.1@37.105,85.776 pad.1@37.283,109.487 pad.1@37.943,109.487 pad.1@38.143,102.16 pad.1@38.143,103.26 pad.1@38.143,104.36 pad.1@38.143,105.46 pad.1@39.193,101.905 pad.1@39.193,103.175 pad.1@39.193,104.445 pad.1@39.193,105.715 pad.1@43.906,102.032 pad.1@45.487,107.874 pad.1@61.235,111.938 pad.1@61.235,114.478 pad.1@61.235,117.018 pad.1@61.235,119.558 pad.1@61.997,100.355 pad.1@61.997,102.184 pad.1@61.997,105.334 pad.1@61.997,107.366 pad.1@62.505,115.748 pad.1@63.775,114.732 pad.1@63.775,117.018 pad.1@64.029,113.018 pad.1@64.029,118.718 pad.1@65.045,115.748 pad.1@66.273,103.894 pad.1@66.315,111.938 pad.1@66.315,114.478 pad.1@66.315,117.018 pad.1@67.585,113.208 pad.1@67.585,115.748 pad.1@68.377,99.607 pad.1@90.546,100.804 pad.1@90.582,97.968 pad.1@91.774,74.081 pad.1@91.825,84.469 pad.1@92.739,77.389 pad.1@93.019,87.752 pad.1@93.501,75.881 pad.1@93.501,86.244 pad.1@95.506,74.727 pad.1@95.506,85.09 pad.1@96.93,64.502 pad.1@96.626,74.092 pad.1@96.626,74.727 pad.1@96.626,75.362 pad.1@96.626,75.997 pad.1@96.753,83.871 pad.1@96.753,84.506 pad.1@96.753,85.141 pad.1@96.753,85.776 pad.1@97.261,74.092 pad.1@97.261,74.727 pad.1@97.261,75.362 pad.1@97.261,75.997 pad.1@97.388,83.871 pad.1@97.388,84.506 pad.1@97.388,85.141 pad.1@97.388,85.776 pad.1@109.873,28.448 | length 207.2
  Top Layer w0.203: pad.1@43.906,102.032 43.906,99.803 44.471,99.238 60.219,99.238 61.336,100.355 pad.1@61.997,100.355 ; pad.1@91.774,74.081 91.774,74.651 92.104,74.981 93.527,74.981 ; pad.1@92.739,77.389 92.739,76.643 pad.1@93.501,75.881 93.501,75.006 93.527,74.981 ; pad.1@95.506,74.727 95.252,74.981 93.527,74.981
  Top Layer w0.254: pad.1@61.997,105.334 62.251,105.081 62.251,104.318 62.674,103.894 64.791,103.894 ; pad.1@66.273,103.894 64.791,103.894 ; pad.1@68.377,99.607 67.469,99.607 65.68,101.397 65.172,101.397 64.791,101.778 64.791,103.894
  Top Layer w0.305: pad.1@91.825,84.469 91.825,85.065 92.13,85.369 93.552,85.369 ; pad.1@93.019,87.752 93.019,87.046 93.501,86.563 pad.1@93.501,86.244 93.501,85.42 93.552,85.369 ; pad.1@95.506,85.09 95.226,85.369 93.552,85.369
  Top Layer w0.61: pad.1@95.506,74.727 pad.1@95.508,74.725
  Layer 1 w0.762: pad.1@63.922,113.221 69.065,113.221 74.463,107.823 88.179,107.823 90.44,105.562 pad.1@90.44,101.007
  Layer 1 w1.27: pad.1@36.998,75.819 95.509,75.819
  Bottom Layer w0.203: pad.1@96.93,64.502 97.809,64.502
  Bottom Layer w0.406: pad.1@96.93,64.502 96.93,63.83 97.159,63.602 98.48,63.602 99.318,62.763 99.318,52.756 100.385,51.689 107.294,51.689 111.434,47.549 111.434,28.829 111.053,28.448 pad.1@109.873,28.448
  Bottom Layer w0.61: pad.1@90.546,100.804 90.564,100.786 90.564,97.986 pad.1@90.582,97.968
  Bottom Layer w0.762: pad.1@96.93,64.502 97.576,64.502 100.867,67.793 100.867,73.635 99.775,74.727 pad.1@97.261,74.727
$Net4: pad.1@11.451,83.998 pad.1@11.451,86.538 pad.1@11.451,89.078 pad.1@11.451,91.618 pad.1@11.451,94.158 pad.1@11.451,96.698 pad.1@11.451,99.238 pad.1@11.451,101.778 pad.1@11.451,104.318 pad.1@11.451,106.858 pad.1@12.975,82.728 pad.1@12.975,85.268 pad.1@12.975,87.808 pad.1@12.975,90.348 pad.1@12.975,92.888 pad.1@12.975,95.428 pad.1@12.975,97.968 pad.1@12.975,100.508 pad.1@12.975,103.048 pad.1@12.975,105.588 pad.1@14.499,83.998 pad.1@14.499,86.538 pad.1@14.499,89.078 pad.1@14.499,91.618 pad.1@14.499,94.158 pad.1@14.499,96.698 pad.1@14.499,99.238 pad.1@14.499,106.858 pad.1@16.023,82.728 pad.1@16.023,85.268 pad.1@16.023,87.808 pad.1@16.023,90.348 pad.1@16.023,92.888 pad.1@16.023,95.428 pad.1@16.023,97.968 pad.1@17.547,83.998 pad.1@17.547,86.538 pad.1@17.547,89.078 pad.1@17.547,91.618 pad.1@17.547,94.158 pad.1@17.547,96.698 pad.1@17.547,99.238 pad.1@17.547,106.858 pad.1@19.071,82.728 pad.1@19.071,85.268 pad.1@19.071,92.888 pad.1@19.071,95.428 pad.1@19.071,97.968 pad.1@19.267,87.554 pad.1@19.267,88.824 pad.1@19.267,90.094 pad.1@19.267,91.364 pad.1@19.325,102.978 pad.1@20.317,87.809 pad.1@20.317,88.909 pad.1@20.317,90.009 pad.1@20.317,91.109 pad.1@20.595,83.998 pad.1@20.595,86.538 pad.1@20.595,94.158 pad.1@20.595,96.698 pad.1@20.595,99.238 pad.1@20.595,106.858 pad.1@21.417,87.809 pad.1@21.417,88.909 pad.1@21.417,90.009 pad.1@21.417,91.109 pad.1@22.119,82.728 pad.1@22.119,85.268 pad.1@22.119,92.888 pad.1@22.119,95.428 pad.1@22.119,97.968 pad.1@22.517,87.809 pad.1@22.517,88.909 pad.1@22.517,90.009 pad.1@22.517,91.109 pad.1@23.643,83.998 pad.1@23.643,86.538 pad.1@23.643,89.078 pad.1@23.643,91.618 pad.1@23.643,94.158 pad.1@23.643,96.698 pad.1@23.643,99.238 pad.1@23.643,106.858 pad.1@25.167,92.888 pad.1@25.167,95.428 pad.1@25.167,97.968 pad.1@25.167,100.508 pad.1@25.167,103.048 pad.1@25.167,105.588 pad.1@26.691,94.158 pad.1@26.691,96.698 pad.1@26.691,99.238 pad.1@26.691,101.778 pad.1@26.691,104.318 pad.1@26.691,106.858 pad.1@28.215,100.508 pad.1@28.215,103.048 pad.1@28.215,105.588 pad.1@29.739,104.318 pad.1@29.739,106.858 pad.1@31.263,103.302 pad.1@31.263,105.588 pad.1@32.787,106.858 pad.1@33.293,103.175 pad.1@33.293,104.445 pad.1@33.293,105.715 pad.1@72.377,99.607 pad.1@73.004,102.997 pad.1@73.286,102.072 | length 51.1
  Top Layer w0.203: pad.1@72.377,99.607 72.377,100.465 73.283,101.371 pad.1@73.283,102.069
  Top Layer w0.254: pad.1@73.283,102.069 pad.1@73.286,102.072
  Top Layer w0.406: pad.1@73.004,102.997 73.283,102.718 pad.1@73.283,102.074
  Top Layer w0.61: pad.1@73.283,102.074 pad.1@73.286,102.072
  Layer 1 w0.61: 29.124,101.727 31.156,99.695 63.093,99.695 65.963,102.565 67.97,102.565 69.722,104.318 71.683,104.318 pad.1@73.004,102.997
$Net5: pad.1@97.811,125.204 pad.1@98.066,121.954 pad.1@98.066,123.054 pad.1@98.066,124.154 pad.1@98.785,120.574 pad.1@99.081,125.204 pad.1@99.166,121.954 pad.1@99.166,123.054 pad.1@99.166,124.154 pad.1@100.055,120.574 pad.1@100.265,121.954 pad.1@100.265,123.054 pad.1@100.265,124.154 pad.1@100.351,125.204 pad.1@101.325,120.574 pad.1@101.366,121.954 pad.1@101.366,123.054 pad.1@101.366,124.154 pad.1@101.621,125.204 pad.1@102.595,120.574 pad.1@102.595,121.59 pad.1@102.595,122.606 pad.1@102.595,123.622 pad.1@102.595,124.638 pad.1@102.595,125.654 pad.1@103.865,120.574 pad.1@103.865,121.59 pad.1@103.865,122.606 pad.1@103.865,123.622 pad.1@103.865,124.638 pad.1@103.865,125.654 pad.1@105.135,120.574 pad.1@105.135,121.59 pad.1@105.135,122.606 pad.1@105.135,125.654 pad.1@106.201,124.206 pad.1@106.913,121.59 pad.1@108.183,122.606 pad.1@108.183,123.622 pad.1@108.183,124.638 pad.1@108.183,125.654 pad.1@109.453,122.606 pad.1@109.453,123.622 pad.1@109.453,124.638 pad.1@109.453,125.654 pad.1@111.281,124.206
$Net6: pad.1@18.954,30.404 pad.1@20.595,30.404 pad.1@21.357,30.404 pad.1@24.151,21.868 pad.1@24.913,21.868 pad.1@24.922,30.404 pad.1@26.642,21.868 pad.1@28.977,21.906 pad.1@30.755,21.906 pad.1@31.771,29.018 pad.1@31.771,30.15 pad.1@31.771,30.912 pad.1@32.533,20.106 pad.1@33.783,29.018 pad.1@38.805,24.544 pad.1@40.28,118.702 pad.1@40.28,121.082 pad.1@42.439,46.152 pad.1@42.439,118.702 pad.1@44.217,118.702 pad.1@44.979,118.702 pad.1@46.689,25.705 pad.1@47.604,25.705 pad.1@49.524,24.544 pad.1@51.583,15.418 pad.1@51.591,16.129 pad.1@52.191,17.391 pad.1@57.425,40.564 pad.1@59.811,17.391 pad.1@65.741,16.729 pad.1@65.917,37.683 pad.1@66.425,35.636 pad.1@67.19,92.061 pad.1@68.051,92.964 pad.1@68.254,39.483 pad.1@68.432,93.345 pad.1@69.006,92.073 pad.1@69.377,94.703 pad.1@69.661,16.721 pad.1@70.887,27.915 pad.1@71.389,32.664 pad.1@71.645,27.915 pad.1@72.75,27.9 pad.1@73.471,16.721 pad.1@73.548,35.636 pad.1@73.562,41.199 pad.1@73.573,39.929 pad.1@75.417,28.648 pad.1@75.417,35.648 pad.1@75.417,42.148 pad.1@77.004,35.382 pad.1@77.281,16.721 pad.1@77.745,35.382 pad.1@80.395,55.154 pad.1@81.091,16.721 pad.1@82.063,84.252 pad.1@82.825,84.252 pad.1@83.291,54.407 pad.1@84.129,84.328 pad.1@84.901,16.721 pad.1@85.805,54.852 pad.1@85.983,84.317 pad.1@86.923,49.849 pad.1@87.411,47.142 pad.1@87.634,28.042 pad.1@87.786,45.199 pad.1@87.786,45.758 pad.1@87.888,23.785 pad.1@87.911,25.654 pad.1@88.218,28.042 pad.1@88.711,16.721 pad.1@90.072,92.594 pad.1@90.191,93.904 pad.1@90.191,94.666 pad.1@91.8,45.809 pad.1@92.098,21.143 pad.1@92.409,45.809 pad.1@92.521,16.721 pad.1@92.898,21.143 pad.1@92.911,47.142 pad.1@93.247,49.824 pad.1@93.349,63.602 pad.1@93.349,64.502 pad.1@93.698,21.143 pad.1@93.794,16.713 pad.1@94.378,16.713 pad.1@94.498,21.143 pad.1@94.911,25.654 pad.1@96.524,24.039 pad.1@96.905,34.148 pad.1@96.905,40.648 pad.1@97.565,24.054 pad.1@99.382,37.363 pad.1@99.843,88.062 pad.1@99.843,89.078 pad.1@99.843,90.348 pad.1@99.843,91.618 pad.1@99.991,37.363 pad.1@100.018,34.315 pad.1@100.044,38.481 pad.1@100.375,89.992 pad.1@100.859,88.062 pad.1@100.859,89.078 pad.1@100.859,90.348 pad.1@100.859,91.618 pad.1@101.02,86.219 pad.1@101.742,44.018 pad.1@101.742,45.695 pad.1@101.742,47.346 pad.1@101.749,36.993 pad.1@101.749,40.803 pad.1@101.749,44.613 pad.1@101.749,48.423 pad.1@101.863,32.643 pad.1@101.888,28.91 pad.1@101.888,30.789 pad.1@103.001,41.288 pad.1@103.052,45.098 pad.1@103.128,37.478 pad.1@103.585,41.288 pad.1@103.653,37.516 pad.1@103.711,45.14 pad.1@106.151,48.235 pad.1@108.64,32.614 pad.1@109.224,32.614 pad.1@109.898,26.568 pad.1@110.57,75.832 pad.1@110.57,114.973 pad.1@110.215,76.238 pad.1@110.215,76.772 pad.1@110.215,114.44 pad.1@110.435,32.969 pad.1@110.435,34.773 pad.1@110.435,36.398 pad.1@110.435,39.198 pad.1@110.486,71.12 pad.1@110.486,72.974 pad.1@110.486,74.752 pad.1@110.511,77.914 pad.1@110.511,109.55 pad.1@110.511,111.455 pad.1@110.511,113.259 pad.1@110.536,116.078 pad.1@111.18,26.568 pad.1@111.18,27.127 pad.1@118.204,12.446 pad.1@119.553,12.446 pad.1@119.714,21.514 pad.1@119.714,22.073 pad.1@120.349,13.411 pad.1@121.125,14.554 pad.1@123.12,14.569 pad.1@138.995,59.498 pad.1@140.697,59.447 pad.1@142.747,59.207 pad.1@144.166,53.721 pad.1@144.251,56.236 pad.1@146.042,7.671 pad.1@146.042,10.211 pad.1@146.042,12.751 pad.1@146.042,15.291 pad.1@146.105,8.941 pad.1@146.852,11.049 pad.1@149.305,11.049 pad.1@152.059,57.508 pad.1@152.085,59.21 | length 300.5
  Top Layer w0.203: pad.1@73.573,39.929 73.573,41.188 pad.1@73.562,41.199 73.562,41.3 74.41,42.148 pad.1@75.417,42.148 ; pad.1@80.395,55.154 80.395,55.016 81.005,54.407 pad.1@83.291,54.407 84.942,54.407 85.399,54.864 pad.1@85.817,54.864 ; pad.1@85.87,54.864 pad.1@85.817,54.864 ; pad.1@87.405,47.137 pad.1@87.411,47.142 87.411,49.855 pad.1@86.923,49.849 87.522,49.849 88.015,50.343 88.015,52.718 pad.1@85.805,54.852 pad.1@85.817,54.864 ; pad.1@87.911,25.654 pad.1@87.911,25.677 ; pad.1@88.218,28.042 88.218,26.772 87.911,26.464 pad.1@87.911,25.677 ; pad.1@88.371,23.774 pad.1@87.888,23.785 87.913,23.811 87.913,25.679 pad.1@87.911,25.677 ; pad.1@92.098,21.143 pad.1@92.898,21.143 pad.1@93.698,21.143 pad.1@94.498,21.143 95.061,21.143 95.305,21.387 95.305,24.003 ; pad.1@92.917,47.092 pad.1@92.911,47.142 92.911,48.838 93.247,49.174 pad.1@93.247,49.824 ; pad.1@94.911,25.654 94.911,24.727 95.305,24.333 95.305,24.003 ; pad.1@96.905,34.148 99.851,34.148 pad.1@100.018,34.315 100.639,34.315 100.944,34.011 100.944,32.944 101.248,32.639 101.859,32.639 pad.1@101.863,32.643 pad.1@101.888,32.618 ; pad.1@96.905,40.648 98.421,40.648 98.785,40.284 98.785,39.065 99.369,38.481 pad.1@100.044,38.481 ; pad.1@97.565,24.054 97.551,24.039 pad.1@96.524,24.039 96.513,24.028 95.33,24.028 95.305,24.003 ; pad.1@101.731,45.568 pad.1@101.742,45.695 ; pad.1@101.731,47.244 pad.1@101.742,47.346 ; pad.1@110.418,36.424 pad.1@110.435,36.398 ; pad.1@110.418,39.167 pad.1@110.435,39.198 ; pad.1@110.486,71.12 pad.1@110.486,72.974 110.57,73 110.57,74.676 pad.1@110.486,74.752 110.57,74.828 pad.1@110.57,75.832 110.57,77.876 110.549,77.876 pad.1@110.511,77.914 ; pad.1@110.511,109.55 pad.1@110.511,111.455 pad.1@110.511,113.259 110.57,113.386 pad.1@110.57,114.973 110.57,115.976 pad.1@110.536,116.078 ; pad.1@146.042,8.941 pad.1@146.105,8.941
  Top Layer w0.254: pad.1@30.755,21.906 30.755,21.226 30.975,21.006 32.279,21.006 32.533,20.752 pad.1@32.533,20.106 ; pad.1@71.645,27.915 71.659,27.9 pad.1@72.75,27.9 73.726,27.9 74.474,28.648 pad.1@75.417,28.648 ; pad.1@73.548,35.636 73.56,35.648 pad.1@75.417,35.648 76.738,35.648 pad.1@77.004,35.382 ; pad.1@87.405,47.137 87.405,46.139 pad.1@87.786,45.758 pad.1@87.786,45.199 ; pad.1@91.8,45.809 pad.1@92.409,45.809 92.549,45.809 92.911,46.171 pad.1@92.911,47.142
  Top Layer w0.305: pad.1@67.949,92.862 pad.1@68.051,92.964 67.416,92.964 67.19,92.738 pad.1@67.19,92.061 67.203,92.073 pad.1@69.006,92.073 pad.1@69.377,92.19 ; pad.1@68.432,93.345 68.635,93.345 69.377,94.087 pad.1@69.377,94.703 ; pad.1@100.018,34.315 100.055,34.352 100.055,37.3 pad.1@99.991,37.363 100.044,37.416 pad.1@100.044,38.481 ; pad.1@100.385,90.002 pad.1@100.375,89.992 100.375,87.538 101.02,86.893 pad.1@101.02,86.219
  Top Layer w0.406: pad.1@18.954,30.404 pad.1@20.595,30.404 ; pad.1@21.357,30.404 pad.1@24.922,30.404 ; pad.1@24.913,21.868 pad.1@26.642,21.868 26.661,21.887 28.958,21.887 pad.1@28.977,21.906 pad.1@30.755,21.906 ; pad.1@31.771,30.15 pad.1@31.771,29.018 pad.1@33.783,29.018 ; pad.1@31.771,30.912 35.073,30.912 38.805,27.179 pad.1@38.805,24.544 ; pad.1@47.604,25.705 49.153,25.705 49.524,25.334 pad.1@49.524,24.544 ; pad.1@68.051,92.964 pad.1@68.432,93.345 ; pad.1@82.825,84.252 82.825,84.328 pad.1@84.129,84.328 84.14,84.317 pad.1@85.983,84.317 ; pad.1@90.072,92.594 90.191,92.594 pad.1@90.191,93.904 ; pad.1@101.742,44.018 pad.1@101.742,45.695 ; pad.1@101.742,47.346 pad.1@101.742,45.695 ; pad.1@101.888,28.91 pad.1@101.888,30.789 pad.1@101.888,32.618 ; pad.1@103.052,45.098 102.455,45.695 pad.1@101.742,45.695 ; pad.1@146.042,7.671 146.042,8.941 pad.1@146.042,15.291
  Top Layer w0.508: pad.1@99.382,37.363 pad.1@99.991,37.363 ; pad.1@110.215,76.238 pad.1@110.215,76.772 ; pad.1@110.215,114.44 110.215,114.617 pad.1@110.57,114.973
  Top Layer w0.61: pad.1@108.64,32.614 109.554,32.614 109.91,32.969 pad.1@110.435,32.969 pad.1@110.435,34.773 pad.1@110.435,36.398 110.418,36.415 pad.1@110.418,39.167
  Bottom Layer w0.203: pad.1@65.851,16.721 67.111,17.981 67.111,19.152 67.39,19.431 70.972,19.431 ; pad.1@69.661,16.721 69.811,16.721 70.946,17.856 70.946,19.406 70.972,19.431 ; pad.1@73.471,16.721 73.621,16.721 74.756,17.856 74.756,19.406 74.731,19.431 ; pad.1@77.281,16.721 77.431,16.721 78.592,17.882 78.592,19.38 78.541,19.431 ; pad.1@81.091,16.721 81.292,16.721 82.402,17.831 82.402,19.406 82.376,19.431 ; pad.1@84.901,16.721 85.051,16.721 86.186,17.856 86.186,19.406 86.212,19.431 ; pad.1@88.711,16.721 88.861,16.721 90.022,17.882 90.022,19.406 89.996,19.431 ; pad.1@92.521,16.721 92.529,16.713 pad.1@93.794,16.713 ; pad.1@93.349,63.602 pad.1@93.349,64.502 ; pad.1@94.378,16.713 94.378,18.809 93.755,19.431 89.996,19.431 ; 119.562,20.422 119.626,20.269 119.638,20.258 119.638,19.736 119.232,19.329 119.232,14.935 119.613,14.554 pad.1@121.125,14.554 ; pad.1@120.349,13.411 pad.1@120.434,13.327 ; pad.1@138.995,59.498 140.646,59.498 pad.1@140.697,59.447 141.471,59.447 141.711,59.207 pad.1@142.747,59.207 ; pad.1@144.166,53.721 pad.1@144.166,56.236 ; pad.1@144.251,56.236 pad.1@144.166,56.236 ; pad.1@152.059,57.508 152.085,57.534 pad.1@152.085,59.21 152.085,60.339 151.744,60.681 143.489,60.681 142.752,59.944 142.752,59.212 pad.1@142.747,59.207 ; 70.972,19.431 74.731,19.431 ; 74.731,19.431 78.541,19.431 ; 78.541,19.431 82.376,19.431 ; 82.376,19.431 86.212,19.431 ; 86.212,19.431 89.996,19.431 ; pad.1@142.747,59.207 142.772,59.182 143.539,59.182 144.166,58.555 pad.1@144.166,56.236
  Bottom Layer w0.254: pad.1@57.425,40.564 60.219,40.564 63.1,37.683 pad.1@65.917,37.683 ; pad.1@66.425,35.636 66.425,36.322 65.917,36.83 pad.1@65.917,37.683 ; pad.1@68.254,39.483 67.3,39.483 67.085,39.268 67.085,37.897 66.857,37.668 65.932,37.668 pad.1@65.917,37.683 ; pad.1@71.389,32.664 72.8,32.664 74.197,31.267 74.197,28.372 73.74,27.915 pad.1@71.645,27.915
  Bottom Layer w0.305: pad.1@40.28,121.082 pad.1@40.28,118.702 pad.1@42.439,118.702 pad.1@44.217,118.702 ; pad.1@52.191,17.391 52.191,18.312 52.465,18.586 59.421,18.586 59.811,18.197 pad.1@59.811,17.391 ; pad.1@109.898,26.568 pad.1@111.18,26.568 ; 119.562,20.422 119.562,21.361 pad.1@119.714,21.514
  Bottom Layer w0.406: pad.1@51.591,16.129 51.591,16.792 pad.1@52.191,17.391 ; pad.1@101.749,36.993 102.234,37.478 pad.1@103.128,37.478 ; pad.1@101.749,40.803 102.234,41.288 pad.1@103.001,41.288 ; pad.1@101.749,44.613 101.948,44.613 102.434,45.098 pad.1@103.052,45.098 ; pad.1@101.749,48.423 105.963,48.423 pad.1@106.151,48.235 ; pad.1@118.204,12.446 pad.1@119.553,12.446 120.434,13.327 121.125,14.017 pad.1@121.125,14.554 123.12,14.554 pad.1@123.12,14.569 ; pad.1@146.852,11.049 pad.1@149.305,11.049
